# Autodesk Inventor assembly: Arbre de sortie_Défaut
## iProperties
Shininess: 64.0
Length Units: 11269
Angle Units: 11279
Time Units: 11290
Mass Units: 11283
Length Display Precision: 3
Angle Display Precision: 2
Compacted: True
Created: 2006-01
Part Number: Arbre de sortie_Défaut
Document SubType Name: Assembly
Designer: Fricot
Density: 0.0
Volumn: 0.0
Area: 0.0
PropertySet Name: Model Information
Control State: 0
Master: False
Checked Out: False
Author: Fricot
